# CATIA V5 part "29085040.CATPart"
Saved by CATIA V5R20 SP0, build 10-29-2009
Part number: 29085040
Definition: NONE
Nomenclature: 29085040
Source: Unknown
Description: 29085040
Bounding box of the stored display mesh (mm): x -20 to 44.548, y -56.5 to 91.048, z -46.5 to 46.5
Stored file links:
  C:\Users\Utente\Desktop\IO LAVORO\3D X SITO CF\X SITO\PLASTICA\RF1\29085040.CATPart
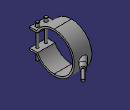
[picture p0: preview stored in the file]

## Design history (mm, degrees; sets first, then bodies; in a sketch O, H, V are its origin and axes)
Body1 "29085040" (main body)
  Solid1: solid without history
